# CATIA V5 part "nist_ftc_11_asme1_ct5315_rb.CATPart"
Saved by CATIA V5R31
Part number: nist_ftc_11_asme1
Nomenclature: nist_ftc_11_asme1
Source: Unknown
Bounding box of the stored display mesh (mm): x -31.5 to 31.5, y -31.5 to 31.5, z -1.5 to 1.479
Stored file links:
  E:\users\dgn\TPS V5\Import-export annotations\Step\PMI representation 2015\NIST UC\FTC\SFA results - 21x export\nist_ftc_11_asme1_ct5315_rb.CATPart
  E:\users\dgn\TPS V5\Import-export annotations\Step\PMI representation 2015\NIST UC\FTC\R29\nist_ftc_10_asme1_ct5293_rb.CATPart
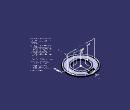
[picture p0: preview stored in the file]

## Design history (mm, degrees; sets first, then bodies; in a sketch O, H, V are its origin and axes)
TTRSSet1
f4a2d38f3ddc11d3a929006094b99c4b_11 "CATTPSSet"
AxisSystem1: origin (0, 0, -1.5), X (1, 0, 0), Y (0, 1, 0), Z (0, 0, 1)
Set1
  Point1: type Center, Curve edge [face of Solid1 | face of Solid1]
  Extract1: ExtractElem face of Solid1
  Extract2: ExtractElem face of Solid1
  Join1: Elements (Extract1; Extract2), ElementsToFederate (face of Solid1; face of Solid1)
Body1 "Solid1" (main body)
  Solid1: solid without history
  Point2: (0, 39, 1.925), in AxisSystem1
  Sketch1 "Main View" on face of Solid1, origin (0, 39, 0.425), H (-1, 0, 0), V (0, -1, 0)
    point P1 (-7.4032, 13.718)
    point P2 (-3.6213, 14.0874)
    point P3 (-1.8676, 14.7028)
    point P4 (-0.4275, 14.8928)
    point P5 (-0.1216, 14.5869)
    point P6 (-6.5345, 13.718)
    point P7 (-7.4032, 13.718)
    point P8 (-6.5345, 16.8662)
    point P9 (-6.5345, 13.718)
    point P10 (-6.2721, 16.9685)
    point P11 (-6.5345, 16.8662)
    point P12 (-3.6213, 14.0874)
    point P13 (-6.2721, 16.9685)
    point P14 (-1.8676, 17.918)
    point P15 (-1.8676, 14.7028)
    point P16 (-2.7447, 17.918)
    point P17 (-1.8676, 17.918)
    point P18 (-2.7447, 14.7237)
    point P19 (-2.7447, 17.918)
    point P20 (-2.9456, 14.6352)
    point P21 (-2.7447, 14.7237)
    point P22 (-5.8198, 17.7433)
    point P23 (-2.9456, 14.6352)
    point P24 (-5.8198, 17.7433)
    point P25 (-7.4032, 17.1234)
    point P26 (-7.4032, 13.718)
    point P27 (-7.4032, 17.1234)
    point P28 (-0.4275, 17.918)
    point P29 (-1.3045, 17.918)
    point P30 (-0.4275, 14.8928)
    point P31 (-0.4275, 17.918)
    point P32 (3.9977, 14.5869)
    point P33 (-0.1216, 14.5869)
    point P34 (3.9977, 14.5869)
    point P35 (3.9816, 15.3755)
    point P36 (1.447, 15.3755)
    point P37 (3.9816, 15.3755)
    point P38 (1.3507, 17.918)
    point P39 (1.447, 15.3755)
    point P40 (8.5197, 17.918)
    point P41 (1.3507, 17.918)
    point P42 (8.5197, 17.0329)
    point P43 (8.5197, 17.918)
    point P44 (6.7251, 17.0329)
    point P45 (8.5197, 17.0329)
    point P46 (6.7251, 13.718)
    point P47 (6.7251, 17.0329)
    point P48 (5.8564, 13.718)
    point P49 (6.7251, 13.718)
    point P50 (5.8564, 17.0329)
    point P51 (5.8564, 13.718)
    point P52 (1.4631, 17.0329)
    point P53 (5.8564, 17.0329)
    point P54 (1.4631, 17.0329)
    point P55 (1.4309, 16.2444)
    point P56 (4.1264, 16.2444)
    point P57 (1.4309, 16.2444)
    point P58 (4.1264, 13.718)
    point P59 (4.1264, 16.2444)
    point P60 (-0.1297, 13.718)
    point P61 (4.1264, 13.718)
    point P62 (-1.3045, 14.8928)
    point P63 (-0.1297, 13.718)
    point P64 (-1.3045, 17.918)
    point P65 (-1.3045, 14.8928)
    line L1 (-1.3045, 17.918) -> (-1.3045, 14.8928)
    arc A1 centre (-0.1297, 14.8928) radius 1.1748 from (-1.3045, 14.8928) to (-0.1297, 13.718) ccw
    line L2 (-0.1297, 13.718) -> (4.1264, 13.718)
    arc A2 centre (3.9253, 14.9812) radius 1.2791 from (4.1264, 13.718) to (4.1264, 16.2444) ccw
    line L3 (4.1264, 16.2444) -> (1.4309, 16.2444)
    arc A3 centre (1.4309, 16.6393) radius 0.3949 from (1.4631, 17.0329) to (1.4309, 16.2444) ccw
    line L4 (1.4631, 17.0329) -> (5.8564, 17.0329)
    line L5 (5.8564, 17.0329) -> (5.8564, 13.718)
    line L6 (5.8564, 13.718) -> (6.7251, 13.718)
    line L7 (6.7251, 13.718) -> (6.7251, 17.0329)
    line L8 (6.7251, 17.0329) -> (8.5197, 17.0329)
    line L9 (8.5197, 17.0329) -> (8.5197, 17.918)
    line L10 (8.5197, 17.918) -> (1.3507, 17.918)
    arc A4 centre (1.3507, 16.6449) radius 1.2731 from (1.3507, 17.918) to (1.447, 15.3755) ccw
    line L11 (1.447, 15.3755) -> (3.9816, 15.3755)
    arc A5 centre (3.9472, 14.9803) radius 0.3967 from (3.9977, 14.5869) to (3.9816, 15.3755) ccw
    line L12 (3.9977, 14.5869) -> (-0.1216, 14.5869)
    line L13 (-0.4275, 14.8928) -> (-0.4275, 17.918)
    line L14 (-0.4275, 17.918) -> (-1.3045, 17.918)
    line L15 (-7.4032, 13.718) -> (-7.4032, 17.1234)
    arc A6 centre (-6.4901, 17.1234) radius 0.9131 from (-5.8198, 17.7433) to (-7.4032, 17.1234) ccw
    line L16 (-5.8198, 17.7433) -> (-2.9456, 14.6352)
    arc A7 centre (-2.8604, 14.714) radius 0.1161 from (-2.9456, 14.6352) to (-2.7447, 14.7237) ccw
    line L17 (-2.7447, 14.7237) -> (-2.7447, 17.918)
    line L18 (-2.7447, 17.918) -> (-1.8676, 17.918)
    line L19 (-1.8676, 17.918) -> (-1.8676, 14.7028)
    line L20 (-3.6213, 14.0874) -> (-6.2721, 16.9685)
    arc A8 centre (-6.3834, 16.8662) radius 0.1512 from (-6.2721, 16.9685) to (-6.5345, 16.8662) ccw
    line L21 (-6.5345, 16.8662) -> (-6.5345, 13.718)
    line L22 (-6.5345, 13.718) -> (-7.4032, 13.718)
    arc A9 centre (-0.1216, 14.8928) radius 0.3059 from (-0.4275, 14.8928) to (-0.1216, 14.5869) ccw
    arc A10 centre (-2.8524, 14.7028) radius 0.9848 from (-3.6213, 14.0874) to (-1.8676, 14.7028) ccw
    distance P1 H = 13.718
    distance P1 V = 7.4032
    coincidence: P2 P12, P3 P15, P4 P30, P5 P33, P6 P9, P7 P26, P8 P11, P10 P13, P14 P17, P16 P19, P18 P21, P20 P23, P22 P24, P25 P27, P28 P31, P29 P64, P32 P34, P35 P37, P36 P39, P38 P41, P40 P43, P42 P45, P44 P47, P46 P49, P48 P51, P50 P53, P52 P54, P55 P57, P56 P59, P58 P61, P60 P63, P62 P65
  Pocket1: profile Sketch1, direction (0, 0, -1), length 1
  Fillet1: radius 0.1, on edge [face of Solid1 | face of Solid1] (x4)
